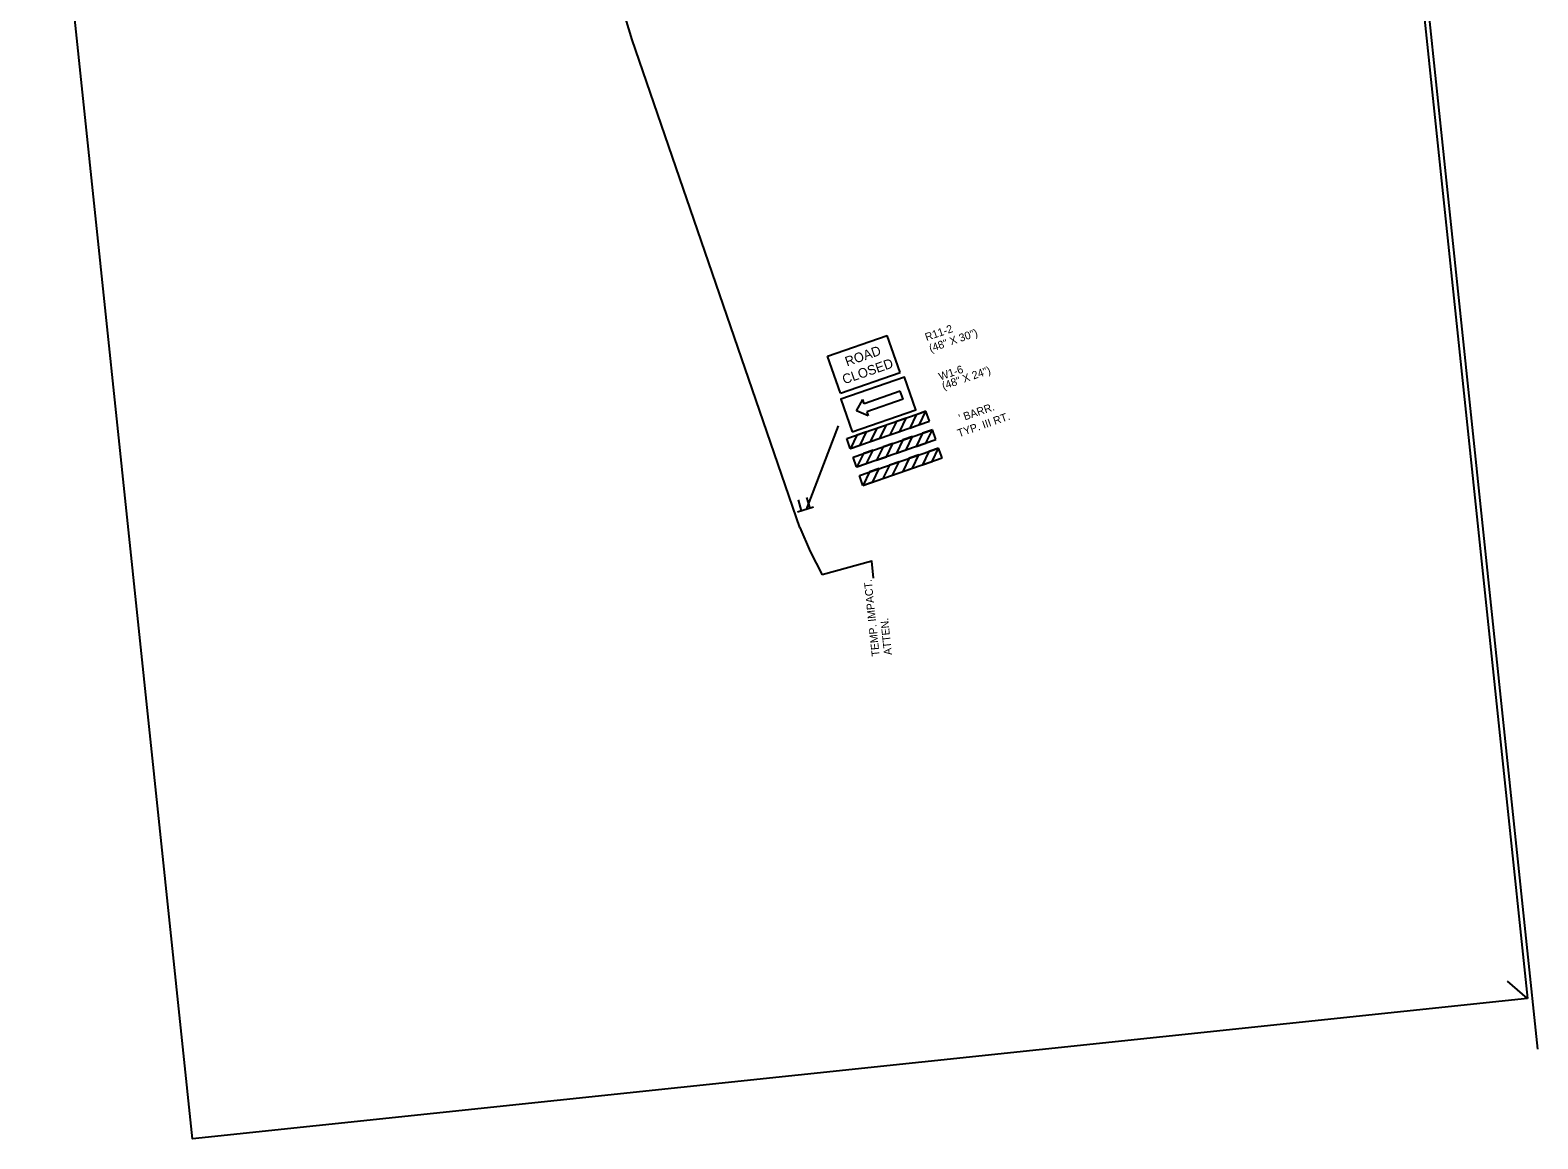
# Model space of a CAD drawing. Extents: x 633427 to 634998, y 288285 to 294065.
# Drawn here: x 633427 to 634580, y 292338 to 293187 of the extents above; entities that cross this region are included whole.
import ezdxf

# ---------------------------------------------------------------- set-up
doc = ezdxf.new("R2010")
doc.units = 0
for name, color, linetype in [('Proposed Surface', 7, 'Continuous'), ('R_Vert Alg Annot', 7, 'Continuous'), ('S_BASELINE', 7, 'Continuous'), ('S_BRIDGE', 7, 'Continuous')]:
    doc.layers.add(name, color=color, linetype=linetype)

msp = doc.modelspace()

# ---------------------------------------------------------------- linework, layer by layer
at = {"layer": 'Proposed Surface'}
for p, q in [((634036.8, 292937.2), (634082.4, 292953)), ((634092.3, 292924.5), (634082.4, 292953)), ((634046.6, 292908.7), (634036.8, 292937.2)), ((634046.6, 292908.7), (634092.3, 292924.5)), ((634092.4, 292910.3), (634064.7, 292900.7)), ((634094.6, 292904.1), (634092.4, 292910.3)), ((634051.5, 292874), (634112, 292894.9)), ((634058.9, 292895.3), (634063.6, 292903.8)), ((634067.9, 292891.4), (634058.9, 292895.3)), ((634064.7, 292900.7), (634063.6, 292903.8)), ((634094.6, 292904.1), (634066.8, 292894.5)), ((634066.8, 292894.5), (634067.9, 292891.4)), ((634114.6, 292887.3), (634112, 292894.9)), ((634054.1, 292866.4), (634114.6, 292887.3)), ((634114.6, 292887.3), (634114.6, 292887.4)), ((634054.1, 292866.4), (634051.5, 292874)), ((634056.3, 292859.9), (634116.9, 292880.8)), ((634058.9, 292852.3), (634119.5, 292873.2)), ((634119.5, 292873.2), (634116.9, 292880.8)), ((634119.5, 292873.2), (634116.9, 292880.8)), ((634058.9, 292852.3), (634056.3, 292859.9)), ((634061.2, 292845.8), (634121.7, 292866.7)), ((634124.4, 292859.2), (634121.7, 292866.7)), ((634063.8, 292838.2), (634124.4, 292859.2)), ((634063.8, 292838.2), (634061.2, 292845.8)), ((634016.9, 292818.7), (634014.4, 292827)), ((634023.4, 292820.7), (634020.8, 292829)), ((634025.9, 292821.5), (634013.8, 292817.8))]:
    msp.add_line(p, q, dxfattribs=at)
for points in [[(634055.6, 292879.2), (634104.3, 292896.1), (634095.7, 292921), (634047, 292904.2)], [(634112, 292894.9), (634104.6, 292892.3), (634099.6, 292882.1), (634107, 292884.7)], [(634081.7, 292884.4), (634074.3, 292881.8), (634069.4, 292871.7), (634076.8, 292874.2)], [(634096.9, 292889.7), (634089.4, 292887.1), (634084.5, 292876.9), (634091.9, 292879.5)], [(634066.6, 292879.2), (634059.2, 292876.6), (634054.2, 292866.4), (634061.7, 292869)], [(634101.7, 292875.6), (634094.3, 292873), (634089.4, 292862.8), (634096.8, 292865.4)], [(634116.9, 292880.8), (634109.4, 292878.2), (634104.5, 292868), (634111.9, 292870.6)], [(634071.5, 292865.1), (634064.1, 292862.5), (634059.1, 292852.3), (634066.5, 292854.9)], [(634086.6, 292870.3), (634079.2, 292867.7), (634074.2, 292857.6), (634081.7, 292860.1)], [(634106.6, 292861.5), (634099.2, 292858.9), (634094.2, 292848.8), (634101.6, 292851.3)], [(634121.7, 292866.7), (634114.3, 292864.1), (634109.3, 292854), (634116.8, 292856.5)], [(634076.3, 292851.1), (634068.9, 292848.5), (634064, 292838.3), (634071.4, 292840.9)], [(634091.5, 292856.3), (634084, 292853.7), (634079.1, 292843.5), (634086.5, 292846.1)]]:
    msp.add_lwpolyline(points, close=True, dxfattribs=at)
at = {"layer": 'R_Vert Alg Annot'}
for p, q in [((634044.9, 292883.7), (634020.4, 292819.8)), ((634015.4, 292805.9), (634023.4, 292787.6)), ((634023.4, 292787.6), (634032.6, 292769.8)), ((634572.3, 292445.3), (634557.1, 292458.6))]:
    msp.add_line(p, q, dxfattribs=at)
for points in [[(634015.4, 292805.9), (633887.2, 293179.3), (633877.7, 293210.7), (633868.5, 293236.5), (633853.8, 293270.4), (633844.2, 293295.9), (633833.2, 293332.4), (633828.8, 293351.2), (633823.5, 293377.7), (633820, 293404.7), (633817.8, 293427), (633815.6, 293455.1), (633814.1, 293488.3), (633813.9, 293522), (633814.8, 293560.2), (633816.8, 293610.1), (633820.8, 293700.4), (633824, 293787), (633827, 293874.2)], [(634071.9, 292767.2), (634070.5, 292780.1), (634032.6, 292769.8)]]:
    msp.add_lwpolyline(points, dxfattribs=at)
at = {"layer": 'S_BASELINE'}
msp.add_lwpolyline([(634572.3, 292445.3), (633550.9, 292338), (633426.6, 293520.7), (633475.7, 293525.9), (633455.2, 293720.6), (633469.8, 293722.1), (633447.2, 293936.5), (634405, 294037.1)], close=True, dxfattribs=at)
at = {"layer": 'S_BRIDGE'}
msp.add_line((634580.2, 292406.6), (634405.9, 294064.7), dxfattribs=at)

# ---------------------------------------------------------------- texts
at = {"layer": 'Proposed Surface'}
for s, height, p in [('R11-2', 6, (634112.5, 292948.6)), ('(48" X 30")', 6, (634115.6, 292940)), ('ROAD', 7.31, (634051.6, 292929.2)), ('CLOSED', 7.35, (634049.5, 292915.5)), ('W1-6', 6, (634123, 292918.4)), ('(48" X 24")', 6, (634125.5, 292911.3)), ("  ' BARR.", 6, (634134.1, 292885.2)), ('TYP. III RT.', 6, (634137.3, 292875))]:
    msp.add_text(s, height=height, rotation=19.0552, dxfattribs=at).set_placement(p)
at = {"layer": 'R_Vert Alg Annot'}
for s, p in [('TEMP. IMPACT.', (634076.6, 292707.6)), ('ATTEN.', (634086, 292708.6))]:
    msp.add_text(s, height=6, rotation=96, dxfattribs=at).set_placement(p)

doc.saveas('drawing.dxf')
